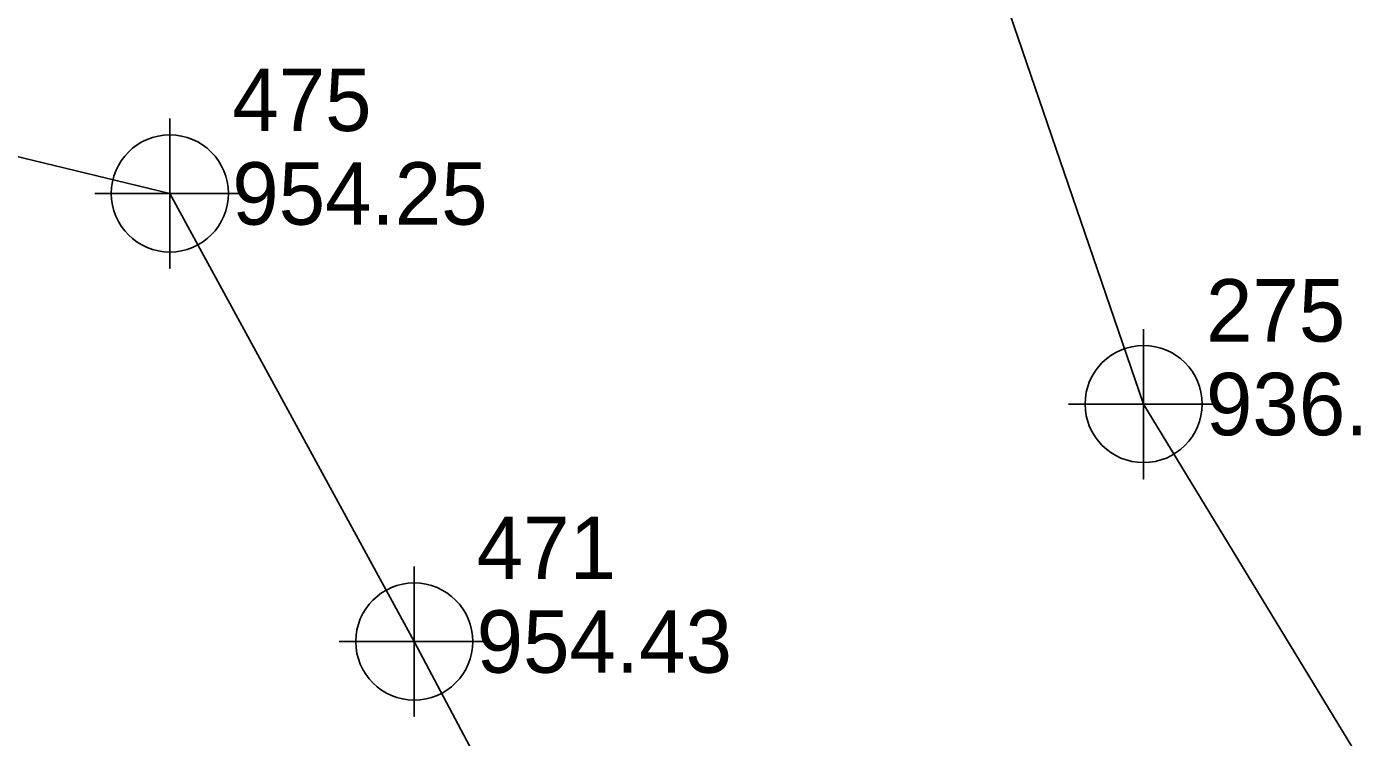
# Model space of a CAD drawing. Extents: x 1150279 to 1151282, y 654632 to 657999.
# Drawn here: x 1150713.8 to 1150767.1, y 657071.3 to 657099.7 of the extents above; entities that cross this region are included whole.
import ezdxf

# ---------------------------------------------------------------- set-up
doc = ezdxf.new("R2010")
doc.units = 0
for name, color, linetype in [('Exist Hydro Jurisdictional Stream or Body of Water', 7, 'Continuous'), ('Exist Hydro Stream or Body of Water Cogo Elevation', 7, 'Continuous'), ('Exist Hydro Stream or Body of Water Cogo Number', 7, 'Continuous'), ('Exist Hydro Stream or Body of Water Cogo Point CELL', 7, 'Continuous'), ('Exist Other Culture Fence Line', 7, 'Continuous'), ('Exist Other Culture Fence Line Cogo Elevation', 7, 'Continuous'), ('Exist Other Culture Fence Line Cogo Number', 7, 'Continuous'), ('Exist Other Culture Fence Line Cogo Point CELL', 7, 'Continuous')]:
    doc.layers.add(name, color=color, linetype=linetype)

msp = doc.modelspace()

# ---------------------------------------------------------------- linework, layer by layer
at = {"layer": 'Exist Hydro Jurisdictional Stream or Body of Water'}
msp.add_lwpolyline([(1150745.794, 657124.778), (1150745.928, 657121.277), (1150758.485, 657084.636), (1150780.666, 657048.192), (1150800.517, 657025.21), (1150816.79, 656993.868)], dxfattribs=at)
at = {"layer": 'Exist Hydro Stream or Body of Water Cogo Point CELL'}
msp.add_lwpolyline([(1150755.485, 657084.636), (1150761.485, 657084.636), (1150758.485, 657084.636), (1150758.485, 657081.636), (1150758.485, 657087.636)], dxfattribs=at)
msp.add_circle((1150758.485, 657084.636), 2.344, dxfattribs=at)
at = {"layer": 'Exist Other Culture Fence Line'}
msp.add_lwpolyline([(1150771.144, 656993.524), (1150752.14, 657032.017), (1150729.275, 657075.13), (1150719.487, 657093.066), (1150693.827, 657099.275)], dxfattribs=at)
at = {"layer": 'Exist Other Culture Fence Line Cogo Point CELL'}
for points in [[(1150719.487, 657096.066), (1150719.487, 657090.066), (1150719.487, 657093.066), (1150722.487, 657093.066), (1150716.487, 657093.066)], [(1150729.275, 657078.13), (1150729.275, 657072.13), (1150729.275, 657075.13), (1150732.275, 657075.13), (1150726.275, 657075.13)]]:
    msp.add_lwpolyline(points, dxfattribs=at)
for centre in [(1150719.487, 657093.066), (1150729.275, 657075.13)]:
    msp.add_circle(centre, 2.344, dxfattribs=at)

# ---------------------------------------------------------------- texts
at = {"layer": 'Exist Hydro Stream or Body of Water Cogo Elevation'}
msp.add_text('936.66', height=2.5, dxfattribs=at).set_placement((1150760.985, 657083.386))
at = {"layer": 'Exist Hydro Stream or Body of Water Cogo Number'}
msp.add_text('275', height=2.5, dxfattribs=at).set_placement((1150760.985, 657087.136))
at = {"layer": 'Exist Other Culture Fence Line Cogo Elevation'}
for s, p in [('954.25', (1150721.987, 657091.816)), ('954.43', (1150731.775, 657073.88))]:
    msp.add_text(s, height=2.5, dxfattribs=at).set_placement(p)
at = {"layer": 'Exist Other Culture Fence Line Cogo Number'}
for s, p in [('475', (1150721.987, 657095.566)), ('471', (1150731.775, 657077.63))]:
    msp.add_text(s, height=2.5, dxfattribs=at).set_placement(p)

doc.saveas('drawing.dxf')
